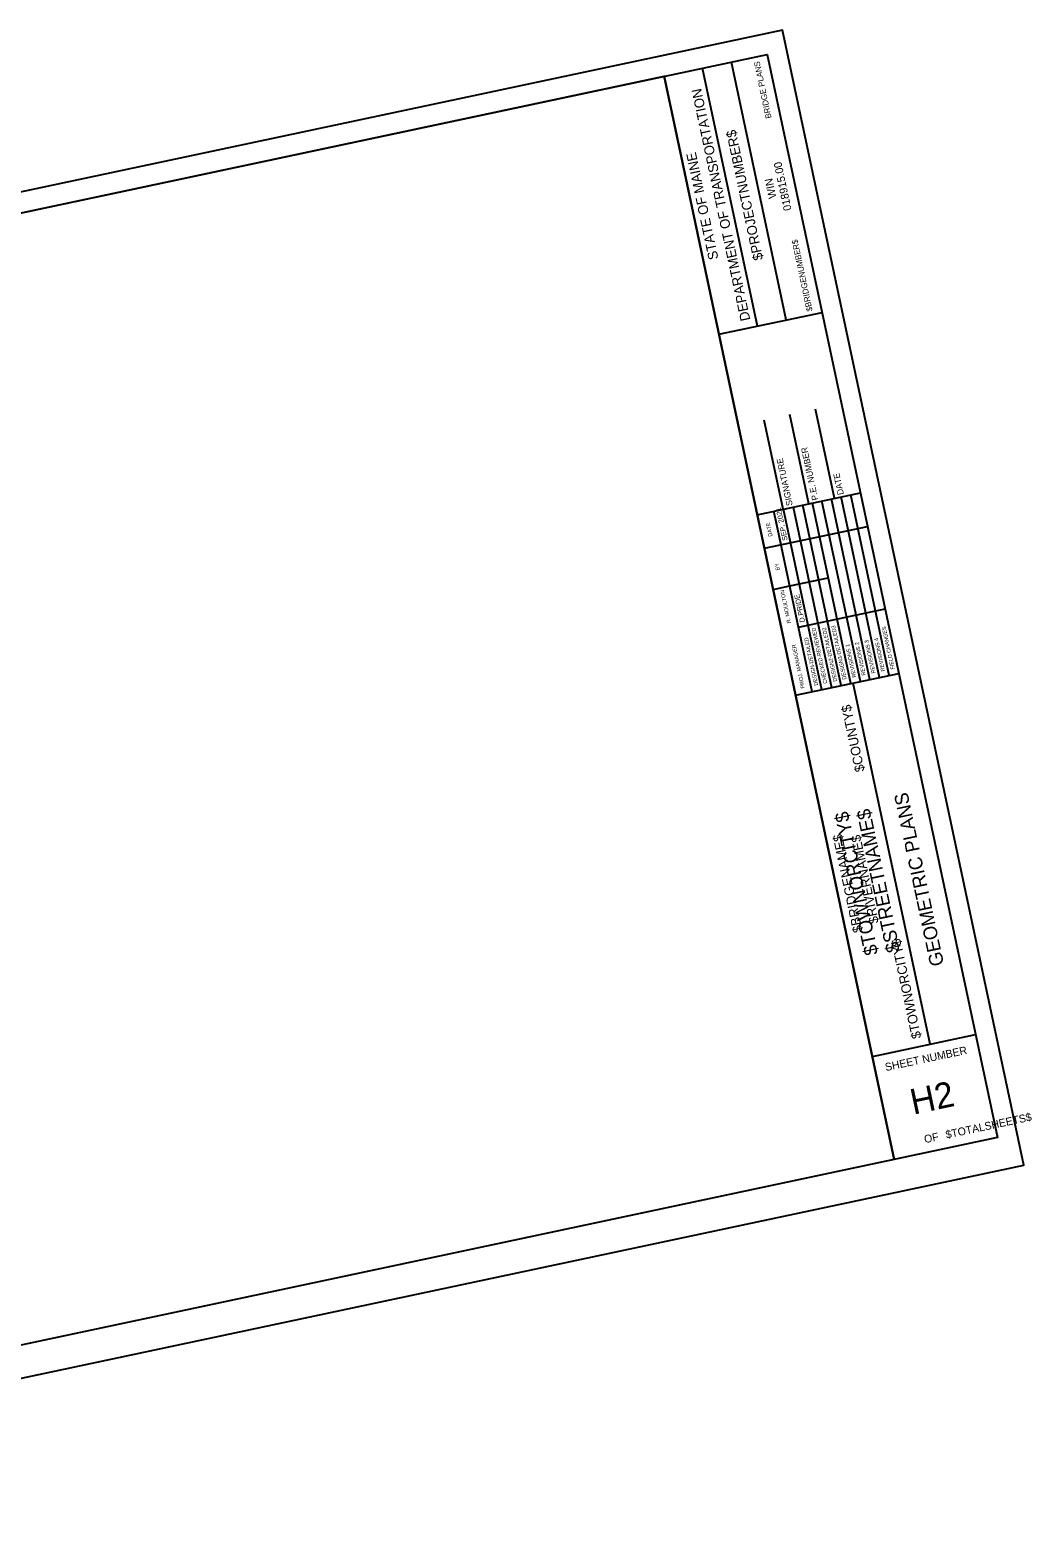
# Model space of a CAD drawing. Extents: x 1742668 to 1743618, y 462122 to 462837.
# Drawn here: x 1743143 to 1743618, y 462122 to 462837 of the extents above; entities that cross this region are included whole.
import ezdxf

# ---------------------------------------------------------------- set-up
doc = ezdxf.new("R2010")
doc.units = 0
for name, color, linetype in [('ANNOTATION', 7, 'Continuous'), ('D_Roadway_Centerline_Flags', 7, 'Continuous'), ('DIMENSIONS', 7, 'Continuous'), ('M_Fencing', 7, 'Continuous'), ('M_Misc_MiscItems', 7, 'Continuous')]:
    doc.layers.add(name, color=color, linetype=linetype)

msp = doc.modelspace()

# ---------------------------------------------------------------- linework, layer by layer
at = {"layer": 'DIMENSIONS'}
for p, q in [((1743487.49, 462696.47), (1743461.5, 462818.73)), ((1743501.16, 462699.37), (1743475.17, 462821.64)), ((1743552.41, 462301.34), (1743443.26, 462814.87)), ((1743469.26, 462692.58), (1743518.16, 462702.97)), ((1743499.67, 462609.63), (1743490.68, 462651.92)), ((1743511.89, 462612.23), (1743502.9, 462654.52)), ((1743524.12, 462614.83), (1743515.13, 462657.12)), ((1743487.44, 462607.03), (1743536.35, 462617.43)), ((1743505.63, 462521.44), (1743554.54, 462531.84)), ((1743569.36, 462356.08), (1743532.97, 462527.25)), ((1743542.02, 462350.27), (1743590.92, 462360.66))]:
    msp.add_line(p, q, dxfattribs=at)
msp.add_lwpolyline([(1742709.65, 462658.94), (1743492.17, 462825.27), (1743601.32, 462311.74), (1742818.8, 462145.41)], close=True, dxfattribs=at)
for points in [[(1743545.43, 462529.92), (1743527.24, 462615.49)], [(1743549.98, 462530.88), (1743531.79, 462616.46)], [(1743498.71, 462592.81), (1743495.34, 462608.71)], [(1743518.09, 462524.1), (1743499.9, 462609.68)], [(1743504.45, 462610.65), (1743522.64, 462525.07)], [(1743527.2, 462526.04), (1743509.01, 462611.62)], [(1743531.76, 462527.01), (1743513.57, 462612.58)], [(1743536.31, 462527.98), (1743518.12, 462613.55)], [(1743540.87, 462528.95), (1743522.68, 462614.52)], [(1743490.82, 462591.14), (1743539.72, 462601.53)], [(1743513.53, 462523.14), (1743496.07, 462605.26)], [(1743494.98, 462571.57), (1743502.88, 462573.25)], [(1743502.87, 462573.25), (1743521.1, 462577.13)], [(1743507.03, 462553.69), (1743548.04, 462562.4)]]:
    msp.add_lwpolyline(points, dxfattribs=at)
at = {"layer": 'M_Fencing'}
msp.add_lwpolyline([(1742782.4, 462122.04), (1743613.83, 462298.76), (1743499.47, 462836.74), (1742668.05, 462660.02)], close=True, dxfattribs=at)
at = {"layer": 'M_Misc_MiscItems'}
msp.add_lwpolyline([(1742709.65, 462658.94), (1743443.26, 462814.87), (1743552.41, 462301.34), (1742818.8, 462145.41)], close=True, dxfattribs=at)

# ---------------------------------------------------------------- texts
at = {"layer": 'ANNOTATION'}
for s, height, p in [('BRIDGE PLANS', 2.795, (1743494.26, 462795.17)), ('$BRIDGENUMBER$', 2.795, (1743513.7, 462703.74)), ('$COUNTY$', 4.536, (1743538.39, 462485.63)), ('$BRIDGENAME$', 4.5358, (1743537.44, 462409.45)), ('$RIVERNAME$', 4.5358, (1743545.11, 462413.71)), ('$TOWNORCITY$', 4.5358, (1743565.27, 462359.17))]:
    msp.add_text(s, height=height, rotation=102, dxfattribs=at).set_placement(p)
at = {"layer": 'D_Roadway_Centerline_Flags'}
for s, p in [('$TOWNORCITY$', (1743544.82, 462398.95)), ('$STREETNAME$', (1743555.21, 462400.24))]:
    msp.add_text(s, height=6.5214, rotation=102, dxfattribs=at).set_placement(p)
at = {"layer": 'DIMENSIONS'}
for s, height, rotation, p in [('DEPARTMENT OF TRANSPORTATION', 4.6588, 102, (1743484.2, 462699.39)), ('$PROJECTNUMBER$', 4.6588, 102, (1743490.28, 462728.15)), ('STATE OF MAINE', 4.6588, 102, (1743469.08, 462728.41)), ('018915.00', 3.726, 102, (1743503.72, 462751.55)), ('WIN', 3.726, 102, (1743496.57, 462757.35)), ('P.E. NUMBER', 2.9528, 102, (1743516.39, 462614.17)), ('SIGNATURE', 2.953, 102, (1743504.26, 462611.59)), ('DATE', 2.953, 102, (1743528.52, 462616.74)), ('SEP. 2021', 2.423, 102, (1743501.87, 462595)), ('DATE', 1.857, 102, (1743494.74, 462596.85)), ('BY', 1.857, 102, (1743498.14, 462580.86)), ('R. MOULTON', 1.864, 102, (1743503.47, 462555.76)), ('D.PRIDE', 2.423, 102, (1743510.11, 462556.25)), ('CHECKED-REVIEWED', 1.8637, 102, (1743520.68, 462527.14)), ('DESIGN2-DETAILED2', 1.8637, 102, (1743525.42, 462528.14)), ('DESIGN3-DETAILED3', 1.8637, 102, (1743529.79, 462529.07)), ('FIELD CHANGES', 1.8637, 102, (1743552.58, 462533.92)), ('PROJ. MANAGER', 1.8637, 102, (1743510.03, 462524.87)), ('DESIGN-DETAILED', 1.8637, 102, (1743516.31, 462526.21)), ('REVISIONS 1', 1.8637, 102, (1743534.35, 462530.04)), ('REVISIONS 2', 1.8637, 102, (1743538.91, 462531.01)), ('REVISIONS 3', 1.8637, 102, (1743543.46, 462531.98)), ('REVISIONS 4', 1.8637, 102, (1743548.02, 462532.95)), ('GEOMETRIC PLANS', 6.5214, 102, (1743576.03, 462393.79)), ('SHEET NUMBER', 3.7264, 12, (1743548.44, 462343.27)), ('H2', 12.097, 12, (1743561.4, 462322.59)), ('$TOTALSHEETS$', 3.7264, 12, (1743577.17, 462311.27)), ('OF', 3.726, 12, (1743566.95, 462309.1))]:
    msp.add_text(s, height=height, rotation=rotation, dxfattribs=at).set_placement(p)

doc.saveas('drawing.dxf')
